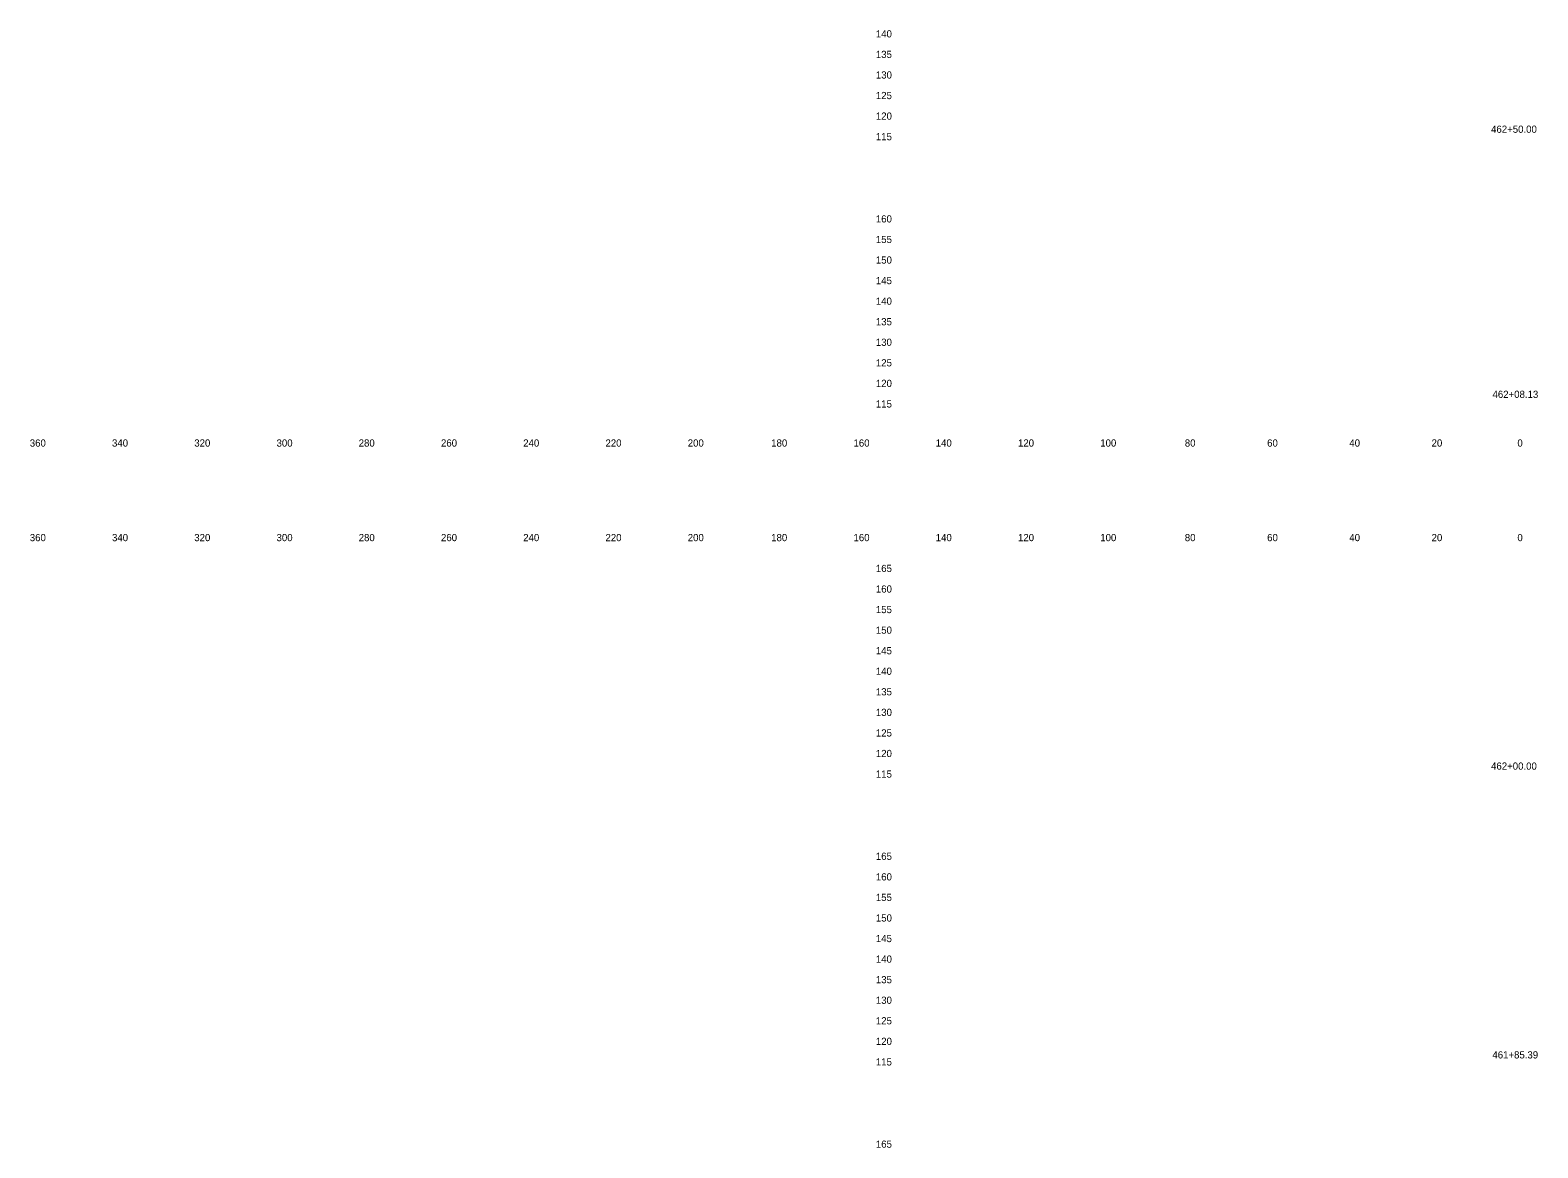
# Model space of a CAD drawing. Extents: x 21281 to 22024, y 6472 to 15198.
# Drawn here: x 21280.5 to 21647.1, y 8374.8 to 8646.6 of the extents above; entities that cross this region are included whole.
import ezdxf

# ---------------------------------------------------------------- set-up
doc = ezdxf.new("R2010")
doc.units = 0
for name, color, linetype in [('Draft_XS_Grid', 7, 'Continuous'), ('Draft_XS_Text', 7, 'Continuous'), ('SLOPE_STAKES_FILL', 7, 'Continuous')]:
    doc.layers.add(name, color=color, linetype=linetype)

msp = doc.modelspace()

# ---------------------------------------------------------------- texts
at = {"layer": 'Draft_XS_Grid'}
for s, p in [('  140  ', (21484.84, 8644.84)), ('  135  ', (21484.84, 8639.84)), ('  130  ', (21484.84, 8634.84)), ('  125  ', (21484.84, 8629.84)), ('  120  ', (21484.84, 8624.84)), ('  115  ', (21484.84, 8619.84)), ('  160  ', (21484.84, 8599.84)), ('  155  ', (21484.84, 8594.84)), ('  150  ', (21484.84, 8589.84)), ('  145  ', (21484.84, 8584.84)), ('  140  ', (21484.84, 8579.84)), ('  135  ', (21484.84, 8574.84)), ('  130  ', (21484.84, 8569.84)), ('  125  ', (21484.84, 8564.84)), ('  120  ', (21484.84, 8559.84)), ('  115  ', (21484.84, 8554.84)), ('  165  ', (21484.84, 8514.84)), ('  160  ', (21484.84, 8509.84)), ('  155  ', (21484.84, 8504.84)), ('  150  ', (21484.84, 8499.84)), ('  145  ', (21484.84, 8494.84)), ('  140  ', (21484.84, 8489.84)), ('  135  ', (21484.84, 8484.84)), ('  130  ', (21484.84, 8479.84)), ('  125  ', (21484.84, 8474.84)), ('  120  ', (21484.84, 8469.84)), ('  115  ', (21484.84, 8464.84)), ('  165  ', (21484.84, 8444.84)), ('  160  ', (21484.84, 8439.84)), ('  155  ', (21484.84, 8434.84)), ('  150  ', (21484.84, 8429.84)), ('  145  ', (21484.84, 8424.84)), ('  140  ', (21484.84, 8419.84)), ('  135  ', (21484.84, 8414.84)), ('  130  ', (21484.84, 8409.84)), ('  125  ', (21484.84, 8404.84)), ('  120  ', (21484.84, 8399.84)), ('  115  ', (21484.84, 8394.84)), ('  165  ', (21484.84, 8374.84))]:
    msp.add_text(s, height=1.75, dxfattribs=at).set_placement(p)
at = {"layer": 'Draft_XS_Text'}
for s, p in [('  360  ', (21279.14, 8545.34)), ('  340  ', (21299.13, 8545.34)), ('  320  ', (21319.13, 8545.34)), ('  300  ', (21339.13, 8545.34)), ('  280  ', (21359.1, 8545.34)), ('  260  ', (21379.11, 8545.34)), ('  240  ', (21399.1, 8545.34)), ('  220  ', (21419.1, 8545.34)), ('  200  ', (21439.1, 8545.34)), ('  180  ', (21459.39, 8545.34)), ('  160  ', (21479.4, 8545.34)), ('  140  ', (21499.39, 8545.34)), ('  120  ', (21519.39, 8545.34)), ('  100  ', (21539.39, 8545.34)), ('  80  ', (21559.95, 8545.34)), ('  60  ', (21579.97, 8545.34)), ('  40  ', (21599.95, 8545.34)), ('  20  ', (21619.95, 8545.34)), ('  0  ', (21640.81, 8545.34)), ('  0  ', (21640.81, 8545.34)), ('  360  ', (21279.14, 8522.34)), ('  340  ', (21299.13, 8522.34)), ('  320  ', (21319.13, 8522.34)), ('  300  ', (21339.13, 8522.34)), ('  280  ', (21359.1, 8522.34)), ('  260  ', (21379.11, 8522.34)), ('  240  ', (21399.1, 8522.34)), ('  220  ', (21419.1, 8522.34)), ('  200  ', (21439.1, 8522.34)), ('  180  ', (21459.39, 8522.34)), ('  160  ', (21479.4, 8522.34)), ('  140  ', (21499.39, 8522.34)), ('  120  ', (21519.39, 8522.34)), ('  100  ', (21539.39, 8522.34)), ('  80  ', (21559.95, 8522.34)), ('  60  ', (21579.97, 8522.34)), ('  40  ', (21599.95, 8522.34)), ('  20  ', (21619.95, 8522.34)), ('  0  ', (21640.81, 8522.34)), ('  0  ', (21640.81, 8522.34))]:
    msp.add_text(s, height=1.75, dxfattribs=at).set_placement(p)
at = {"layer": 'SLOPE_STAKES_FILL'}
for s, p in [('  462+50.00  ', (21634.41, 8621.65)), ('  462+08.13  ', (21634.76, 8557.18)), ('  462+00.00  ', (21634.41, 8466.78)), ('  461+85.39  ', (21634.73, 8396.55))]:
    msp.add_text(s, height=1.75, dxfattribs=at).set_placement(p)

doc.saveas('drawing.dxf')
